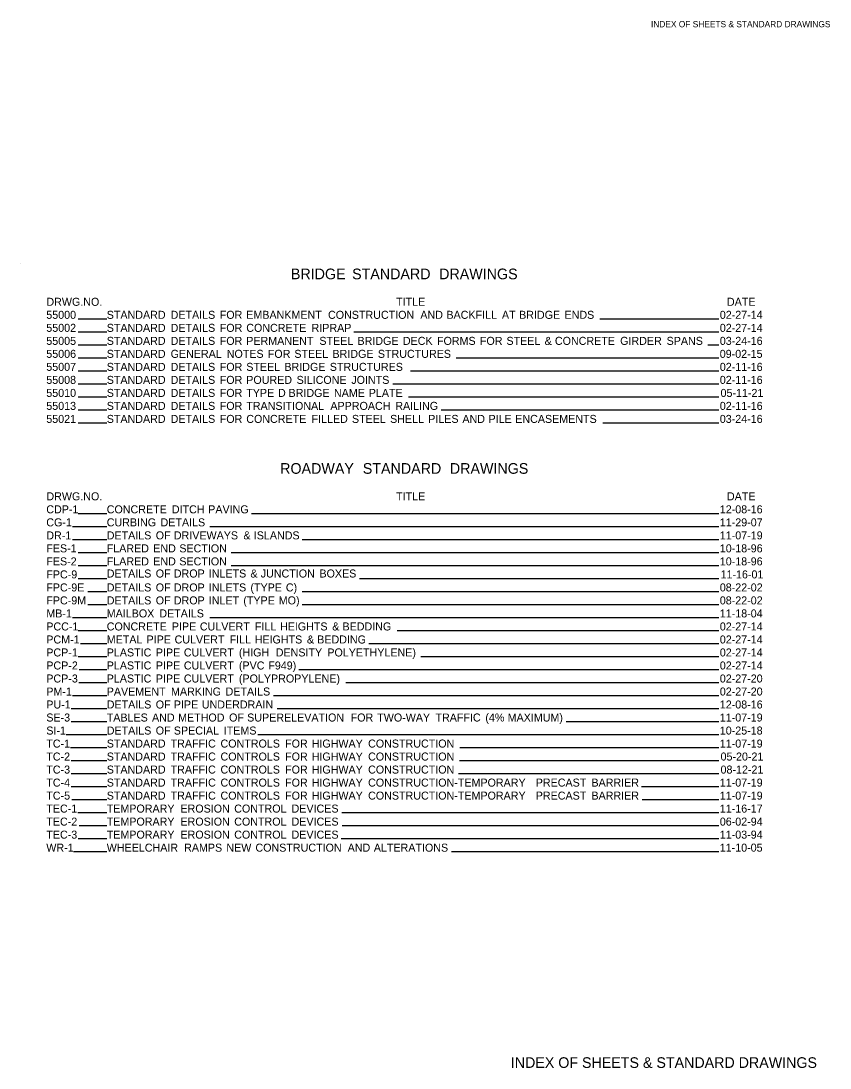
# Model space of a CAD drawing. Extents: x 2 to 32.9, y 0.7 to 21.4.
# Drawn here: x 17.69 to 32.85, y 0.72 to 20.34 of the extents above; entities that cross this region are included whole.
import ezdxf

# ---------------------------------------------------------------- set-up
doc = ezdxf.new("R2010")
doc.units = 0
for name, color, linetype in [('Default', 7, 'Continuous'), ('R_Annotation', 7, 'Continuous'), ('R_Border', 7, 'Continuous')]:
    doc.layers.add(name, color=color, linetype=linetype)

msp = doc.modelspace()

# ---------------------------------------------------------------- linework, layer by layer
at = {"layer": 'Default'}
for p, q in [((17.685, 15.79), (17.685, 15.79)), ((18.761, 14.76), (19.294, 14.76)), ((28.537, 14.76), (30.77, 14.76)), ((18.761, 14.516), (19.294, 14.516)), ((23.929, 14.516), (30.77, 14.516)), ((18.761, 14.272), (19.294, 14.272)), ((30.565, 14.272), (30.77, 14.272)), ((18.761, 14.029), (19.294, 14.029)), ((25.846, 14.029), (30.77, 14.029)), ((18.761, 13.785), (19.294, 13.785)), ((24.989, 13.785), (30.77, 13.785)), ((18.761, 13.541), (19.294, 13.541)), ((24.655, 13.541), (30.77, 13.541)), ((18.761, 13.297), (19.294, 13.297)), ((24.952, 13.297), (30.77, 13.297)), ((18.761, 13.054), (19.294, 13.054)), ((25.564, 13.054), (30.77, 13.054)), ((18.761, 12.81), (19.294, 12.81)), ((28.592, 12.81), (30.77, 12.81)), ((18.761, 11.116), (19.294, 11.116)), ((22.008, 11.116), (30.77, 11.116)), ((18.651, 10.872), (19.294, 10.872)), ((21.225, 10.872), (30.77, 10.872)), ((18.651, 10.628), (19.294, 10.628)), ((22.957, 10.628), (30.77, 10.628)), ((18.761, 10.385), (19.294, 10.385)), ((21.626, 10.385), (30.77, 10.385)), ((18.761, 10.141), (19.294, 10.141)), ((21.626, 10.141), (30.77, 10.141)), ((18.761, 9.897), (19.294, 9.897)), ((24.033, 9.897), (30.77, 9.897)), ((18.942, 9.653), (19.294, 9.653)), ((22.957, 9.653), (30.77, 9.653)), ((18.942, 9.41), (19.294, 9.41)), ((22.957, 9.41), (30.77, 9.41)), ((18.651, 9.166), (19.294, 9.166)), ((21.225, 9.166), (30.77, 9.166)), ((18.761, 8.922), (19.294, 8.922)), ((24.738, 8.922), (30.77, 8.922)), ((18.802, 8.678), (19.294, 8.678)), ((24.21, 8.678), (30.77, 8.678)), ((18.758, 8.435), (19.294, 8.435)), ((25.185, 8.435), (30.77, 8.435)), ((18.78, 8.191), (19.294, 8.191)), ((22.897, 8.191), (30.77, 8.191)), ((18.769, 7.947), (19.293, 7.947)), ((23.777, 7.947), (30.769, 7.947)), ((18.65, 7.703), (19.293, 7.703)), ((22.421, 7.703), (30.769, 7.703)), ((18.628, 7.46), (19.293, 7.46)), ((22.492, 7.46), (30.769, 7.46)), ((18.628, 7.216), (19.293, 7.216)), ((27.907, 7.216), (30.769, 7.216)), ((18.532, 6.972), (19.293, 6.972)), ((22.129, 6.972), (30.769, 6.972)), ((18.613, 6.728), (19.293, 6.728)), ((25.915, 6.728), (30.769, 6.728)), ((18.625, 6.485), (19.293, 6.485)), ((25.907, 6.485), (30.769, 6.485)), ((18.627, 6.241), (19.293, 6.241)), ((25.889, 6.241), (30.769, 6.241)), ((18.63, 5.997), (19.293, 5.997)), ((29.322, 5.997), (30.769, 5.997)), ((18.638, 5.753), (19.293, 5.753)), ((29.331, 5.753), (30.769, 5.753)), ((18.752, 5.51), (19.293, 5.51)), ((23.7, 5.51), (30.769, 5.51)), ((18.775, 5.266), (19.293, 5.266)), ((23.706, 5.266), (30.769, 5.266)), ((18.756, 5.022), (19.293, 5.022)), ((23.687, 5.022), (30.769, 5.022)), ((18.673, 4.778), (19.293, 4.778)), ((25.755, 4.778), (30.769, 4.778))]:
    msp.add_line(p, q, dxfattribs=at)

# ---------------------------------------------------------------- texts
for s, height, p in [('BRIDGE', 0.2, (22.746, 15.501)), (' STANDARD', 0.2, (23.819, 15.501)), (' DRAWINGS', 0.2, (25.451, 15.501)), ('DRWG.NO.', 0.15, (18.163, 15.004)), ('TITLE', 0.15, (24.718, 15.004)), ('DATE', 0.15, (30.921, 15.004)), ('55000', 0.15, (18.161, 14.76)), ('STANDARD', 0.15, (19.294, 14.76)), (' DETAILS', 0.15, (20.436, 14.76)), (' FOR', 0.15, (21.357, 14.76)), (' EMBANKMENT', 0.15, (21.854, 14.76)), (' CONSTRUCTION', 0.15, (23.387, 14.76)), (' AND', 0.15, (25.117, 14.76)), (' BACKFILL', 0.15, (25.606, 14.76)), (' AT', 0.15, (26.647, 14.76)), (' BRIDGE', 0.15, (26.969, 14.76)), (' ENDS', 0.15, (27.82, 14.76)), ('02-27-14', 0.15, (30.787, 14.76)), ('55002', 0.15, (18.161, 14.516)), ('STANDARD', 0.15, (19.294, 14.516)), (' DETAILS', 0.15, (20.436, 14.516)), (' FOR', 0.15, (21.357, 14.516)), (' CONCRETE', 0.15, (21.854, 14.516)), (' RIPRAP', 0.15, (23.078, 14.516)), ('02-27-14', 0.15, (30.787, 14.516)), ('55005', 0.15, (18.161, 14.272)), ('STANDARD', 0.15, (19.294, 14.272)), (' DETAILS', 0.15, (20.436, 14.272)), (' FOR', 0.15, (21.357, 14.272)), (' PERMANENT', 0.15, (21.854, 14.272)), (' STEEL', 0.15, (23.224, 14.272)), (' BRIDGE', 0.15, (23.939, 14.272)), (' DECK', 0.15, (24.79, 14.272)), (' FORMS', 0.15, (25.43, 14.272)), (' FOR', 0.15, (26.234, 14.272)), (' STEEL', 0.15, (26.732, 14.272)), (' &', 0.15, (27.447, 14.272)), (' CONCRETE', 0.15, (27.64, 14.272)), (' GIRDER', 0.15, (28.863, 14.272)), (' SPANS', 0.15, (29.734, 14.272)), ('03-24-16', 0.15, (30.787, 14.272)), ('55006', 0.15, (18.161, 14.029)), ('STANDARD', 0.15, (19.294, 14.029)), (' GENERAL', 0.15, (20.436, 14.029)), (' NOTES', 0.15, (21.488, 14.029)), (' FOR', 0.15, (22.258, 14.029)), (' STEEL', 0.15, (22.755, 14.029)), (' BRIDGE', 0.15, (23.47, 14.029)), (' STRUCTURES', 0.15, (24.321, 14.029)), ('09-02-15', 0.15, (30.786, 14.029)), ('55007', 0.15, (18.161, 13.785)), ('STANDARD', 0.15, (19.294, 13.785)), (' DETAILS', 0.15, (20.436, 13.785)), (' FOR', 0.15, (21.357, 13.785)), (' STEEL', 0.15, (21.854, 13.785)), (' BRIDGE', 0.15, (22.569, 13.785)), (' STRUCTURES', 0.15, (23.42, 13.785)), ('02-11-16', 0.15, (30.787, 13.785)), ('55008', 0.15, (18.161, 13.541)), ('STANDARD', 0.15, (19.294, 13.541)), (' DETAILS', 0.15, (20.436, 13.541)), (' FOR', 0.15, (21.357, 13.541)), (' POURED', 0.15, (21.854, 13.541)), (' SILICONE', 0.15, (22.798, 13.541)), (' JOINTS', 0.15, (23.823, 13.541)), ('02-11-16', 0.15, (30.787, 13.541)), ('55010', 0.15, (18.161, 13.297)), ('STANDARD', 0.15, (19.294, 13.297)), (' DETAILS', 0.15, (20.436, 13.297)), (' FOR', 0.15, (21.357, 13.297)), (' TYPE', 0.15, (21.854, 13.297)), (' D', 0.15, (22.449, 13.297)), (' BRIDGE', 0.15, (22.647, 13.297)), (' NAME', 0.15, (23.498, 13.297)), (' PLATE', 0.15, (24.15, 13.297)), ('05-11-21', 0.15, (30.801, 13.297)), ('55013', 0.15, (18.161, 13.054)), ('STANDARD', 0.15, (19.294, 13.054)), (' DETAILS', 0.15, (20.436, 13.054)), (' FOR', 0.15, (21.357, 13.054)), (' TRANSITIONAL', 0.15, (21.854, 13.054)), (' APPROACH', 0.15, (23.431, 13.054)), (' RAILING', 0.15, (24.648, 13.054)), ('02-11-16', 0.15, (30.787, 13.054)), ('55021', 0.15, (18.161, 12.81)), ('STANDARD', 0.15, (19.294, 12.81)), (' DETAILS', 0.15, (20.436, 12.81)), (' FOR', 0.15, (21.357, 12.81)), (' CONCRETE', 0.15, (21.854, 12.81)), (' FILLED', 0.15, (23.078, 12.81)), (' STEEL', 0.15, (23.835, 12.81)), (' SHELL', 0.15, (24.55, 12.81)), (' PILES', 0.15, (25.265, 12.81)), (' AND', 0.15, (25.906, 12.81)), (' PILE', 0.15, (26.396, 12.81)), (' ENCASEMENTS', 0.15, (26.897, 12.81)), ('03-24-16', 0.15, (30.787, 12.81)), ('ROADWAY', 0.2, (22.545, 11.857)), (' STANDARD', 0.2, (24.02, 11.857)), (' DRAWINGS', 0.2, (25.652, 11.857)), ('DRWG.NO.', 0.15, (18.163, 11.36)), ('TITLE', 0.15, (24.718, 11.36)), ('DATE', 0.15, (30.921, 11.36)), ('CDP-1', 0.15, (18.161, 11.116)), ('CONCRETE', 0.15, (19.294, 11.116)), (' DITCH', 0.15, (20.459, 11.116)), (' PAVING', 0.15, (21.141, 11.116)), ('12-08-16', 0.15, (30.787, 11.116)), ('CG-1', 0.15, (18.161, 10.872)), ('CURBING', 0.15, (19.294, 10.872)), (' DETAILS', 0.15, (20.247, 10.872)), ('11-29-07', 0.15, (30.787, 10.872)), ('DR-1', 0.15, (18.161, 10.628)), ('DETAILS', 0.15, (19.294, 10.628)), (' OF', 0.15, (20.157, 10.628)), (' DRIVEWAYS', 0.15, (20.496, 10.628)), (' &', 0.15, (21.801, 10.628)), (' ISLANDS', 0.15, (21.995, 10.628)), ('11-07-19', 0.15, (30.787, 10.628)), ('FES-1', 0.15, (18.161, 10.385)), ('FLARED', 0.15, (19.294, 10.385)), (' END', 0.15, (20.11, 10.385)), (' SECTION', 0.15, (20.599, 10.385)), ('10-18-96', 0.15, (30.787, 10.385)), ('FES-2', 0.15, (18.161, 10.141)), ('FLARED', 0.15, (19.294, 10.141)), (' END', 0.15, (20.11, 10.141)), (' SECTION', 0.15, (20.599, 10.141)), ('10-18-96', 0.15, (30.787, 10.141)), ('FPC-9', 0.15, (18.161, 9.897)), ('DETAILS', 0.15, (19.294, 9.914)), (' OF', 0.15, (20.157, 9.914)), (' DROP', 0.15, (20.496, 9.914)), (' INLETS', 0.15, (21.151, 9.914)), (' &', 0.15, (21.932, 9.914)), (' JUNCTION', 0.15, (22.125, 9.914)), (' BOXES', 0.15, (23.226, 9.914)), ('11-16-01', 0.15, (30.801, 9.897)), (' (TYPE', 0.15, (21.932, 9.653)), (' C)', 0.15, (22.596, 9.653)), ('FPC-9E', 0.15, (18.161, 9.653)), ('DETAILS', 0.15, (19.294, 9.653)), (' OF', 0.15, (20.157, 9.653)), (' DROP', 0.15, (20.496, 9.653)), (' INLETS', 0.15, (21.151, 9.653)), ('08-22-02', 0.15, (30.787, 9.653)), ('FPC-9M', 0.15, (18.161, 9.41)), ('DETAILS', 0.15, (19.294, 9.41)), (' OF', 0.15, (20.157, 9.41)), (' DROP', 0.15, (20.496, 9.41)), (' INLET', 0.15, (21.151, 9.41)), (' (TYPE', 0.15, (21.799, 9.41)), (' MO)', 0.15, (22.463, 9.41)), ('08-22-02', 0.15, (30.787, 9.41)), ('MB-1', 0.15, (18.161, 9.166)), ('MAILBOX', 0.15, (19.294, 9.166)), (' DETAILS', 0.15, (20.224, 9.166)), ('11-18-04', 0.15, (30.787, 9.166)), ('PCC-1', 0.15, (18.161, 8.922)), ('CONCRETE', 0.15, (19.294, 8.922)), (' PIPE', 0.15, (20.459, 8.922)), (' CULVERT', 0.15, (20.984, 8.922)), (' FILL', 0.15, (22.016, 8.922)), (' HEIGHTS', 0.15, (22.486, 8.922)), (' &', 0.15, (23.465, 8.922)), (' BEDDING', 0.15, (23.658, 8.922)), ('02-27-14', 0.15, (30.787, 8.922)), ('PCM-1', 0.15, (18.161, 8.678)), ('METAL', 0.15, (19.294, 8.678)), (' PIPE', 0.15, (19.985, 8.678)), (' CULVERT', 0.15, (20.51, 8.678)), (' FILL', 0.15, (21.542, 8.678)), (' HEIGHTS', 0.15, (22.012, 8.678)), (' &', 0.15, (22.991, 8.678)), (' BEDDING', 0.15, (23.184, 8.678)), ('02-27-14', 0.15, (30.787, 8.678)), ('PCP-1', 0.15, (18.161, 8.435)), ('PLASTIC', 0.15, (19.294, 8.435)), (' PIPE', 0.15, (20.159, 8.435)), (' CULVERT', 0.15, (20.684, 8.435)), (' (HIGH', 0.15, (21.716, 8.435)), ('  DENSITY', 0.15, (22.351, 8.435)), (' POLYETHYLENE)', 0.15, (23.374, 8.435)), ('02-27-14', 0.15, (30.787, 8.435)), ('PCP-2', 0.15, (18.161, 8.191)), ('PLASTIC', 0.15, (19.294, 8.191)), (' PIPE', 0.15, (20.159, 8.191)), (' CULVERT', 0.15, (20.684, 8.191)), (' (PVC', 0.15, (21.716, 8.191)), (' F949)', 0.15, (22.267, 8.191)), ('02-27-14', 0.15, (30.787, 8.191)), ('PCP-3', 0.15, (18.161, 7.947)), ('PLASTIC', 0.15, (19.294, 7.947)), (' PIPE', 0.15, (20.159, 7.947)), (' CULVERT', 0.15, (20.684, 7.947)), (' (POLYPROPYLENE)', 0.15, (21.716, 7.947)), ('02-27-20', 0.15, (30.787, 7.947)), ('PM-1', 0.15, (18.161, 7.703)), ('PAVEMENT', 0.15, (19.294, 7.703)), (' MARKING', 0.15, (20.443, 7.703)), (' DETAILS', 0.15, (21.466, 7.703)), ('02-27-20', 0.15, (30.787, 7.703)), ('PU-1', 0.15, (18.161, 7.46)), ('DETAILS', 0.15, (19.294, 7.46)), (' OF', 0.15, (20.157, 7.46)), (' PIPE', 0.15, (20.496, 7.46)), (' UNDERDRAIN', 0.15, (21.021, 7.46)), ('12-08-16', 0.15, (30.787, 7.46)), ('SE-3', 0.15, (18.161, 7.216)), ('TABLES', 0.15, (19.294, 7.216)), (' AND', 0.15, (20.087, 7.216)), (' METHOD', 0.15, (20.576, 7.216)), (' OF', 0.15, (21.532, 7.216)), (' SUPERELEVATION', 0.15, (21.871, 7.216)), (' FOR', 0.15, (23.811, 7.216)), (' TWO-WAY', 0.15, (24.309, 7.216)), (' TRAFFIC', 0.15, (25.401, 7.216)), (' (4%', 0.15, (26.336, 7.216)), (' MAXIMUM)', 0.15, (26.754, 7.216)), ('11-07-19', 0.15, (30.787, 7.216)), ('SI-1', 0.15, (18.161, 6.972)), ('DETAILS', 0.15, (19.294, 6.972)), (' OF', 0.15, (20.157, 6.972)), (' SPECIAL', 0.15, (20.496, 6.972)), (' ITEMS', 0.15, (21.432, 6.972)), ('10-25-18', 0.15, (30.787, 6.972)), ('TC-1', 0.15, (18.161, 6.728)), ('STANDARD', 0.15, (19.294, 6.728)), (' TRAFFIC', 0.15, (20.436, 6.728)), (' CONTROLS', 0.15, (21.371, 6.728)), (' FOR', 0.15, (22.582, 6.728)), (' HIGHWAY', 0.15, (23.08, 6.728)), (' CONSTRUCTION', 0.15, (24.138, 6.728)), ('11-07-19', 0.15, (30.787, 6.728)), ('TC-2', 0.15, (18.161, 6.485)), ('STANDARD', 0.15, (19.294, 6.485)), (' TRAFFIC', 0.15, (20.436, 6.485)), (' CONTROLS', 0.15, (21.371, 6.485)), (' FOR', 0.15, (22.582, 6.485)), (' HIGHWAY', 0.15, (23.08, 6.485)), (' CONSTRUCTION', 0.15, (24.138, 6.485)), ('05-20-21', 0.15, (30.801, 6.485)), ('TC-3', 0.15, (18.161, 6.241)), ('STANDARD', 0.15, (19.294, 6.241)), (' TRAFFIC', 0.15, (20.436, 6.241)), (' CONTROLS', 0.15, (21.371, 6.241)), (' FOR', 0.15, (22.582, 6.241)), (' HIGHWAY', 0.15, (23.08, 6.241)), (' CONSTRUCTION', 0.15, (24.138, 6.241)), ('08-12-21', 0.15, (30.801, 6.241)), ('TC-4', 0.15, (18.161, 5.997)), ('STANDARD', 0.15, (19.294, 5.997)), (' TRAFFIC', 0.15, (20.436, 5.997)), (' CONTROLS', 0.15, (21.371, 5.997)), (' FOR', 0.15, (22.582, 5.997)), (' HIGHWAY', 0.15, (23.08, 5.997)), (' CONSTRUCTION-TEMPORARY', 0.15, (24.138, 5.997)), (' PRECAST', 0.15, (27.281, 5.997)), (' BARRIER', 0.15, (28.325, 5.997)), ('11-07-19', 0.15, (30.787, 5.997)), ('TC-5', 0.15, (18.161, 5.753)), ('STANDARD', 0.15, (19.294, 5.753)), (' TRAFFIC', 0.15, (20.436, 5.753)), (' CONTROLS', 0.15, (21.371, 5.753)), (' FOR', 0.15, (22.582, 5.753)), (' HIGHWAY', 0.15, (23.08, 5.753)), (' CONSTRUCTION-TEMPORARY', 0.15, (24.138, 5.753)), (' PRECAST', 0.15, (27.281, 5.753)), (' BARRIER', 0.15, (28.325, 5.753)), ('11-07-19', 0.15, (30.787, 5.753)), ('TEC-1', 0.15, (18.161, 5.51)), ('TEMPORARY', 0.15, (19.294, 5.51)), (' EROSION', 0.15, (20.62, 5.51)), (' CONTROL', 0.15, (21.628, 5.51)), (' DEVICES', 0.15, (22.703, 5.51)), ('11-16-17', 0.15, (30.787, 5.51)), ('TEC-2', 0.15, (18.161, 5.266)), ('TEMPORARY', 0.15, (19.294, 5.266)), (' EROSION', 0.15, (20.62, 5.266)), (' CONTROL', 0.15, (21.628, 5.266)), (' DEVICES', 0.15, (22.703, 5.266)), ('06-02-94', 0.15, (30.787, 5.266)), ('TEC-3', 0.15, (18.161, 5.022)), ('TEMPORARY', 0.15, (19.294, 5.022)), (' EROSION', 0.15, (20.62, 5.022)), (' CONTROL', 0.15, (21.628, 5.022)), (' DEVICES', 0.15, (22.703, 5.022)), ('11-03-94', 0.15, (30.787, 5.022)), ('WR-1', 0.15, (18.161, 4.778)), ('WHEELCHAIR', 0.15, (19.294, 4.778)), (' RAMPS', 0.15, (20.689, 4.778)), (' NEW', 0.15, (21.481, 4.778)), (' CONSTRUCTION', 0.15, (22.026, 4.778)), (' AND', 0.15, (23.755, 4.778)), (' ALTERATIONS', 0.15, (24.245, 4.778)), ('11-10-05', 0.15, (30.786, 4.778))]:
    msp.add_text(s, height=height, dxfattribs=at).set_placement(p)
at = {"layer": 'R_Annotation'}
msp.add_text('INDEX OF SHEETS & STANDARD DRAWINGS', height=0.19962, dxfattribs=at).set_placement((26.869, 0.727))
at = {"layer": 'R_Border'}
msp.add_text('INDEX OF SHEETS & STANDARD DRAWINGS', height=0.11701, dxfattribs=at).set_placement((29.497, 20.222))

doc.saveas('drawing.dxf')
